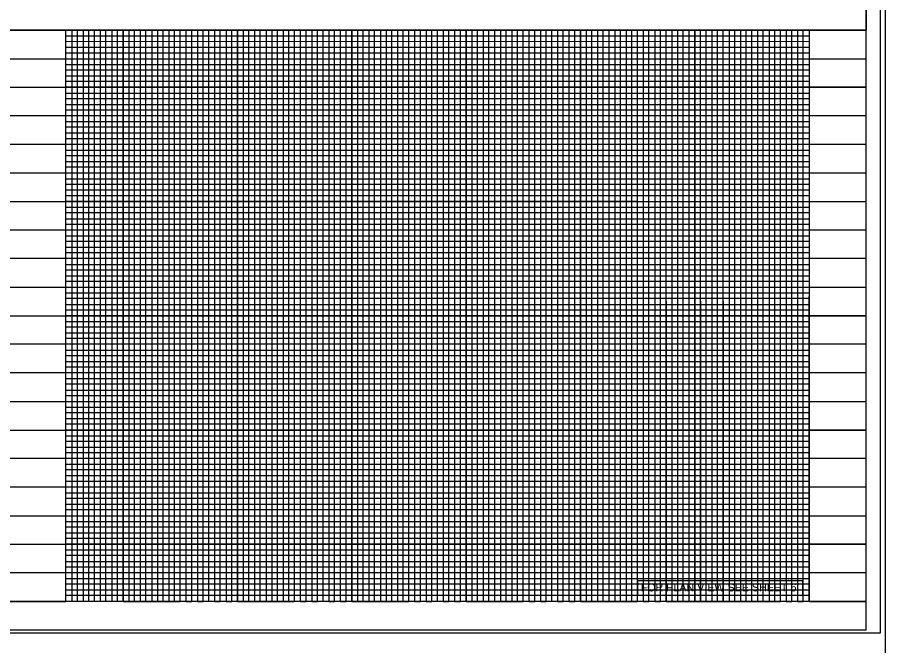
# Model space of a CAD drawing. Extents: x 1755181 to 1757273, y 729911 to 735411.
# Drawn here: x 1756105 to 1756865, y 731022 to 731572 of the extents above; entities that cross this region are included whole.
import ezdxf

# ---------------------------------------------------------------- set-up
doc = ezdxf.new("R2010")
doc.units = 0
for name, color, linetype in [('Prop Grid Mask', 7, 'Continuous'), ('Prop VPI Label', 7, 'Continuous'), ('Scratch_Level_3', 7, 'Continuous'), ('Sheet DOT Grid CELL', 7, 'Continuous'), ('Sheet Plot Border Inside CELL', 7, 'Continuous'), ('Sheet Plot Border Outside CELL', 7, 'Continuous'), ('Sheet Profile CELL', 7, 'Continuous'), ('Sheet Profile Grid Major CELL', 7, 'Continuous'), ('Sheet Profile Grid Middle CELL', 7, 'Continuous'), ('Sheet Profile Grid Minor CELL', 7, 'Continuous')]:
    doc.layers.add(name, color=color, linetype=linetype)

msp = doc.modelspace()

# ---------------------------------------------------------------- linework, layer by layer
at = {"layer": 'Prop Grid Mask'}
msp.add_lwpolyline([(1756647.87, 731079.11), (1756792.01, 731079.11), (1756792.01, 731065.9), (1756647.87, 731065.9)], close=True, dxfattribs=at)
at = {"layer": 'Scratch_Level_3'}
for points in [[(1756097.67, 731560.78), (1756097.67, 732085.78), (1756647.63, 732085.78), (1756647.63, 731852.66), (1756847.68, 731852.66), (1756847.68, 731560.78)], [(1756097.67, 731035.78), (1756847.67, 731035.78), (1756847.67, 731560.78), (1756097.67, 731560.78)]]:
    msp.add_lwpolyline(points, close=True, dxfattribs=at)
at = {"layer": 'Sheet DOT Grid CELL'}
for p, q in [((1755347.67, 731560.78), (1756847.56, 731560.78)), ((1756147.67, 731060.78), (1756147.67, 731560.78)), ((1756197.67, 731060.78), (1756197.67, 731560.78)), ((1756247.67, 731060.78), (1756247.67, 731560.78)), ((1756297.67, 731060.78), (1756297.67, 731560.78)), ((1756347.67, 731060.78), (1756347.67, 731560.78)), ((1756397.67, 731060.78), (1756397.67, 731560.78)), ((1756447.67, 731060.78), (1756447.67, 731560.78)), ((1756497.67, 731060.78), (1756497.67, 731560.78)), ((1756547.67, 731060.78), (1756547.67, 731560.78)), ((1756597.67, 731060.78), (1756597.67, 731560.78)), ((1756697.67, 731060.78), (1756697.67, 731560.78)), ((1756747.67, 731060.78), (1756747.67, 731560.78)), ((1756847.66, 731510.78), (1756147.67, 731510.78)), ((1756647.62, 731460.78), (1756147.67, 731460.78)), ((1756647.67, 731060.78), (1756647.67, 731423.23)), ((1756647.67, 731410.78), (1756147.67, 731410.78)), ((1756797.67, 731060.78), (1756797.67, 731327.66)), ((1756847.67, 731310.78), (1756147.67, 731310.78)), ((1756847.67, 731260.78), (1756147.67, 731260.78)), ((1756847.67, 731210.78), (1756147.67, 731210.78)), ((1756847.67, 731160.78), (1756147.67, 731160.78)), ((1756847.67, 731110.78), (1756147.67, 731110.78))]:
    msp.add_line(p, q, dxfattribs=at)
at = {"layer": 'Sheet Plot Border Inside CELL'}
msp.add_lwpolyline([(1755193.67, 731033.23), (1756860.17, 731033.23), (1756860.17, 732088.33), (1755193.67, 732088.33)], close=True, dxfattribs=at)
at = {"layer": 'Sheet Plot Border Outside CELL'}
msp.add_lwpolyline([(1755180.67, 731010.78), (1756864.67, 731010.78), (1756864.67, 732110.78), (1755180.67, 732110.78)], close=True, dxfattribs=at)
at = {"layer": 'Sheet Profile CELL'}
for p, q in [((1755347.67, 731560.78), (1756847.67, 731560.78)), ((1756847.67, 731060.78), (1755347.67, 731060.78)), ((1755347.67, 731035.78), (1756847.67, 731035.78))]:
    msp.add_line(p, q, dxfattribs=at)
msp.add_lwpolyline([(1756847.67, 732085.78), (1755347.67, 732085.78), (1755347.67, 731035.78), (1756847.67, 731035.78)], close=True, dxfattribs=at)
at = {"layer": 'Sheet Profile Grid Major CELL'}
for p, q in [((1756147.67, 731560.78), (1756197.67, 731560.78)), ((1756247.67, 731560.78), (1756297.67, 731560.78)), ((1756347.67, 731560.78), (1756397.67, 731560.78)), ((1756447.67, 731560.78), (1756497.67, 731560.78)), ((1756547.67, 731560.78), (1756597.67, 731560.78)), ((1756647.67, 731560.78), (1756697.67, 731560.78)), ((1756747.67, 731560.78), (1756797.67, 731560.78)), ((1756747.67, 731060.78), (1756747.67, 731060.78))]:
    msp.add_line(p, q, dxfattribs=at)
for points in [[(1756097.67, 731060.78), (1756147.67, 731060.78), (1756147.67, 731560.78), (1756197.67, 731560.78), (1756197.67, 731060.78), (1756247.67, 731060.78), (1756247.67, 731560.78), (1756297.67, 731560.78), (1756297.67, 731060.78), (1756347.67, 731060.78), (1756347.67, 731560.78), (1756397.67, 731560.78), (1756397.67, 731060.78), (1756447.67, 731060.78), (1756447.67, 731560.78), (1756497.67, 731560.78), (1756497.67, 731060.78), (1756547.67, 731060.78), (1756547.67, 731560.78), (1756597.67, 731560.78), (1756597.67, 731060.78), (1756647.67, 731060.78), (1756647.67, 731560.78), (1756673.97, 731560.78)], [(1756697.67, 731560.78), (1756697.67, 731060.78), (1756747.67, 731060.78), (1756747.67, 731060.78), (1756747.67, 731560.78)], [(1756797.67, 731560.78), (1756797.67, 731060.78), (1756847.67, 731060.78), (1756847.67, 731410.78)], [(1755347.67, 731510.78), (1756847.71, 731510.78)], [(1756847.71, 731460.78), (1755347.67, 731460.78), (1755347.67, 731410.78), (1756847.71, 731410.78)], [(1756847.67, 731360.78), (1755347.67, 731360.78), (1755347.67, 731310.78), (1756847.67, 731310.78)], [(1756847.67, 731260.78), (1755347.67, 731260.78), (1755347.67, 731210.78), (1756847.67, 731210.78)], [(1756847.67, 731160.78), (1755347.67, 731160.78), (1755347.67, 731160.78), (1755347.67, 731110.78), (1756847.67, 731110.78)], [(1756847.67, 731060.78), (1755347.67, 731060.78)]]:
    msp.add_lwpolyline(points, dxfattribs=at)
at = {"layer": 'Sheet Profile Grid Middle CELL'}
for p, q in [((1756172.67, 731060.78), (1756172.67, 731560.78)), ((1756222.67, 731560.78), (1756222.67, 731060.78)), ((1756272.67, 731060.78), (1756272.67, 731560.78)), ((1756322.67, 731560.78), (1756322.67, 731060.78)), ((1756372.67, 731060.78), (1756372.67, 731560.78)), ((1756422.67, 731560.78), (1756422.67, 731060.78)), ((1756472.67, 731060.78), (1756472.67, 731560.78)), ((1756522.67, 731560.78), (1756522.67, 731060.78)), ((1756572.67, 731060.78), (1756572.67, 731560.78)), ((1756622.67, 731560.78), (1756622.67, 731060.78)), ((1756672.67, 731060.78), (1756672.67, 731560.78)), ((1755347.67, 731535.78), (1756847.66, 731535.78))]:
    msp.add_line(p, q, dxfattribs=at)
for points in [[(1756672.67, 731323.58), (1756672.67, 731060.78), (1756722.67, 731060.78), (1756722.67, 731560.78)], [(1756722.67, 731323.58), (1756722.67, 731060.78), (1756772.67, 731060.78), (1756772.67, 731560.78)], [(1756847.71, 731485.78), (1755347.67, 731485.78), (1755347.67, 731435.78), (1756847.71, 731435.78)], [(1756847.66, 731385.78), (1755347.67, 731385.78), (1755347.67, 731335.78), (1756847.67, 731335.78)], [(1756847.67, 731285.78), (1755347.67, 731285.78), (1755347.67, 731235.78), (1756847.67, 731235.78)], [(1756847.67, 731185.78), (1755347.67, 731185.78), (1755347.67, 731135.78), (1756847.67, 731135.78)], [(1756847.67, 731085.78), (1755347.67, 731085.78)]]:
    msp.add_lwpolyline(points, dxfattribs=at)
at = {"layer": 'Sheet Profile Grid Minor CELL'}
for p, q in [((1756152.67, 731560.78), (1756152.67, 731060.78)), ((1756157.67, 731060.78), (1756157.67, 731560.78)), ((1756162.67, 731560.78), (1756162.67, 731060.78)), ((1756167.67, 731060.78), (1756167.67, 731560.78)), ((1756177.67, 731560.78), (1756177.67, 731060.78)), ((1756182.67, 731060.78), (1756182.67, 731560.78)), ((1756187.67, 731560.78), (1756187.67, 731060.78)), ((1756192.67, 731060.78), (1756192.67, 731560.78)), ((1756202.67, 731560.78), (1756202.67, 731060.78)), ((1756207.67, 731060.78), (1756207.67, 731560.78)), ((1756212.67, 731560.78), (1756212.67, 731060.78)), ((1756217.67, 731060.78), (1756217.67, 731560.78)), ((1756227.67, 731560.78), (1756227.67, 731060.78)), ((1756147.67, 731555.78), (1756797.71, 731555.78)), ((1756797.71, 731550.78), (1756147.67, 731550.64)), ((1756147.67, 731545.78), (1756797.71, 731545.78)), ((1756797.66, 731425.78), (1756147.67, 731425.78)), ((1756797.71, 731420.78), (1756147.67, 731420.78)), ((1756797.71, 731415.78), (1756147.67, 731415.78)), ((1756147.67, 731405.78), (1756797.71, 731405.78)), ((1756797.71, 731400.78), (1756147.67, 731400.78)), ((1756147.67, 731395.78), (1756797.66, 731395.78)), ((1756797.66, 731375.78), (1756147.67, 731375.78)), ((1756147.67, 731370.78), (1756797.66, 731370.78)), ((1756797.67, 731350.78), (1756147.67, 731350.78)), ((1756147.67, 731345.78), (1756797.67, 731345.78)), ((1756797.67, 731325.78), (1756147.67, 731325.78)), ((1756147.67, 731320.78), (1756797.67, 731320.78)), ((1756797.67, 731315.78), (1756147.67, 731315.78)), ((1756147.67, 731305.78), (1756797.67, 731305.78)), ((1756797.67, 731300.78), (1756147.67, 731300.78)), ((1756147.67, 731295.78), (1756797.67, 731295.78)), ((1756797.67, 731290.78), (1756147.67, 731290.78)), ((1756147.67, 731280.78), (1756797.67, 731280.78)), ((1756797.67, 731275.78), (1756147.67, 731275.78)), ((1756147.67, 731270.78), (1756797.67, 731270.78)), ((1756797.67, 731265.78), (1756147.67, 731265.78)), ((1756147.67, 731255.78), (1756797.67, 731255.78)), ((1756797.67, 731250.78), (1756147.67, 731250.78)), ((1756147.67, 731245.78), (1756797.67, 731245.78)), ((1756797.67, 731240.78), (1756147.67, 731240.78)), ((1756147.67, 731230.78), (1756797.67, 731230.78)), ((1756797.67, 731225.78), (1756147.67, 731225.78)), ((1756147.67, 731220.78), (1756797.67, 731220.78)), ((1756797.67, 731215.78), (1756147.67, 731215.78)), ((1756147.67, 731205.78), (1756797.67, 731205.78)), ((1756797.67, 731200.78), (1756147.67, 731200.78)), ((1756147.67, 731195.78), (1756797.67, 731195.78)), ((1756797.67, 731190.78), (1756147.67, 731190.78)), ((1756147.67, 731180.78), (1756797.67, 731180.78)), ((1756797.67, 731175.78), (1756147.67, 731175.78)), ((1756797.67, 731170.78), (1756147.67, 731170.78)), ((1756797.67, 731165.78), (1756147.67, 731165.78)), ((1756147.67, 731155.78), (1756797.67, 731155.78)), ((1756797.67, 731150.78), (1756147.67, 731150.78)), ((1756147.67, 731145.78), (1756797.67, 731145.78)), ((1756797.67, 731140.78), (1756147.67, 731140.78)), ((1756147.67, 731130.78), (1756797.67, 731130.78)), ((1756797.67, 731125.78), (1756147.67, 731125.78)), ((1756147.67, 731120.78), (1756797.67, 731120.78)), ((1756797.67, 731115.78), (1756147.67, 731115.78)), ((1756147.67, 731105.78), (1756797.67, 731105.78)), ((1756797.67, 731100.78), (1756147.67, 731100.78)), ((1756147.67, 731095.78), (1756797.67, 731095.78)), ((1756797.67, 731090.78), (1756147.67, 731090.78)), ((1756147.67, 731080.78), (1756797.67, 731080.78)), ((1756797.67, 731075.78), (1756147.67, 731075.78)), ((1756147.67, 731070.78), (1756797.67, 731070.78))]:
    msp.add_line(p, q, dxfattribs=at)
for points in [[(1756232.67, 731060.78), (1756232.67, 731560.78), (1756237.67, 731560.78), (1756237.67, 731060.78), (1756242.67, 731060.78), (1756242.67, 731560.78), (1756252.67, 731560.78), (1756252.67, 731060.78), (1756257.67, 731060.78), (1756257.67, 731560.78), (1756262.67, 731560.78), (1756262.67, 731060.78), (1756267.67, 731060.78), (1756267.67, 731560.78), (1756277.67, 731560.78), (1756277.67, 731060.78), (1756282.67, 731060.78), (1756282.67, 731560.78), (1756287.67, 731560.78), (1756287.67, 731060.78), (1756292.67, 731060.78), (1756292.67, 731560.78), (1756302.67, 731560.78), (1756302.67, 731060.78), (1756307.67, 731060.78), (1756307.67, 731560.78), (1756312.67, 731560.78), (1756312.67, 731060.78), (1756317.67, 731060.78), (1756317.67, 731560.78), (1756327.67, 731560.78), (1756327.67, 731060.78), (1756332.67, 731060.78), (1756332.67, 731560.78), (1756337.67, 731560.78), (1756337.67, 731060.78), (1756342.67, 731060.78), (1756342.67, 731560.78), (1756352.67, 731560.78), (1756352.67, 731060.78), (1756357.67, 731060.78), (1756357.67, 731560.78), (1756362.67, 731560.78), (1756362.67, 731060.78), (1756367.67, 731060.78), (1756367.67, 731560.78), (1756377.67, 731560.78), (1756377.67, 731060.78), (1756382.67, 731060.78), (1756382.67, 731560.78), (1756387.67, 731560.78), (1756387.67, 731060.78), (1756392.67, 731060.78), (1756392.67, 731560.78), (1756402.67, 731560.78), (1756402.67, 731060.78), (1756407.67, 731060.78), (1756407.67, 731560.78), (1756412.67, 731560.78), (1756412.67, 731060.78), (1756417.67, 731060.78), (1756417.67, 731560.78), (1756427.67, 731560.78), (1756427.67, 731060.78), (1756432.67, 731060.78), (1756432.67, 731560.78), (1756437.67, 731560.78), (1756437.67, 731060.78), (1756442.67, 731060.78), (1756442.67, 731560.78), (1756452.67, 731560.78), (1756452.67, 731060.78), (1756457.67, 731060.78), (1756457.67, 731560.78), (1756462.67, 731560.78), (1756462.67, 731060.78), (1756467.67, 731060.78), (1756467.67, 731560.78), (1756477.67, 731560.78), (1756477.67, 731060.78), (1756482.67, 731060.78), (1756482.67, 731560.78), (1756487.67, 731560.78), (1756487.67, 731060.78), (1756492.67, 731060.78), (1756492.67, 731560.78), (1756502.67, 731560.78), (1756502.67, 731060.78), (1756507.67, 731060.78), (1756507.67, 731560.78), (1756512.67, 731560.78), (1756512.67, 731060.78), (1756517.67, 731060.78), (1756517.67, 731560.78), (1756527.67, 731560.78), (1756527.67, 731060.78), (1756532.67, 731060.78), (1756532.67, 731560.78), (1756537.67, 731560.78), (1756537.67, 731060.78)], [(1756537.67, 731060.78), (1756542.67, 731060.78), (1756542.67, 731560.78), (1756552.67, 731560.78), (1756552.67, 731060.78), (1756557.67, 731060.78), (1756557.67, 731560.78), (1756562.67, 731560.78), (1756562.67, 731060.78), (1756567.67, 731060.78), (1756567.67, 731560.78), (1756577.67, 731560.78), (1756577.67, 731060.78), (1756582.67, 731060.78), (1756582.67, 731560.78), (1756587.67, 731560.78), (1756587.67, 731060.78), (1756592.67, 731060.78), (1756592.67, 731560.78), (1756602.67, 731560.78), (1756602.67, 731060.78), (1756607.67, 731060.78), (1756607.67, 731560.78), (1756612.67, 731560.78), (1756612.67, 731060.78), (1756617.67, 731060.78), (1756617.67, 731560.78), (1756627.67, 731560.78), (1756627.67, 731060.78), (1756632.67, 731060.78), (1756632.67, 731560.78), (1756637.67, 731560.78), (1756637.67, 731060.78), (1756642.67, 731060.78), (1756642.67, 731560.78), (1756652.67, 731560.78)], [(1756652.67, 731560.78), (1756652.67, 731060.78), (1756657.67, 731060.78), (1756657.67, 731560.78)], [(1756662.67, 731560.78), (1756662.67, 731060.78), (1756667.67, 731060.78), (1756667.67, 731560.78)], [(1756677.67, 731560.78), (1756677.67, 731060.78), (1756677.67, 731060.78), (1756682.67, 731060.78), (1756687.67, 731060.78), (1756687.67, 731560.78)], [(1756682.67, 731560.78), (1756682.67, 731060.78)], [(1756692.64, 731560.78), (1756692.57, 731060.83), (1756697.57, 731060.83), (1756702.67, 731060.78), (1756702.67, 731560.78)], [(1756702.67, 731323.58), (1756702.67, 731060.78), (1756707.67, 731060.78), (1756707.67, 731560.78)], [(1756712.67, 731560.78), (1756712.67, 731060.78), (1756717.67, 731060.78), (1756717.67, 731560.78)], [(1756727.67, 731560.78), (1756727.67, 731060.78), (1756732.67, 731060.78), (1756732.67, 731560.78)], [(1756737.67, 731560.78), (1756737.67, 731060.78), (1756742.67, 731060.78), (1756742.67, 731560.78)], [(1756752.67, 731560.78), (1756752.67, 731060.78), (1756757.67, 731060.78), (1756757.67, 731560.78)], [(1756762.67, 731560.78), (1756762.67, 731060.78), (1756767.67, 731060.78), (1756767.67, 731560.78)], [(1756777.67, 731560.78), (1756777.67, 731060.78), (1756782.67, 731060.78), (1756782.67, 731560.78)], [(1756787.67, 731560.78), (1756787.67, 731060.78), (1756792.67, 731060.78), (1756792.67, 731560.78)], [(1756797.71, 731540.78), (1756147.67, 731540.78)], [(1756147.67, 731530.78), (1756797.71, 731530.78)], [(1756797.66, 731525.78), (1756147.67, 731525.78)], [(1756147.67, 731520.78), (1756797.71, 731520.78)], [(1756797.71, 731515.78), (1756147.67, 731515.78)], [(1756147.67, 731505.78), (1756797.71, 731505.78)], [(1756797.71, 731500.78), (1756147.67, 731500.78)], [(1756147.67, 731495.78), (1756797.71, 731495.78)], [(1756797.71, 731490.78), (1756147.67, 731490.78)], [(1756147.67, 731480.78), (1756797.71, 731480.78)], [(1756797.71, 731475.78), (1756147.67, 731475.78)], [(1756147.67, 731470.78), (1756797.71, 731470.78)], [(1756797.71, 731465.78), (1756147.67, 731465.78)], [(1756147.67, 731455.78), (1756797.71, 731455.78)], [(1756797.71, 731450.68), (1756147.67, 731450.68)], [(1756147.67, 731445.78), (1756797.71, 731445.78)], [(1756797.71, 731440.78), (1756147.67, 731440.78)], [(1756147.67, 731430.78), (1756797.71, 731430.78)], [(1756797.66, 731390.78), (1756147.67, 731390.78)], [(1756147.67, 731380.78), (1756797.66, 731380.78)], [(1756797.66, 731365.78), (1756147.67, 731365.78)], [(1756147.67, 731355.78), (1756797.67, 731355.78)], [(1756797.67, 731340.78), (1756147.67, 731340.78)], [(1756147.67, 731330.78), (1756797.67, 731330.78)], [(1756797.67, 731065.78), (1756147.67, 731065.78)]]:
    msp.add_lwpolyline(points, dxfattribs=at)

# ---------------------------------------------------------------- texts
at = {"layer": 'Prop VPI Label'}
msp.add_text('FOR PLAN VIEW SEE SHEET 6', height=7, dxfattribs=at).set_placement((1756650.41, 731069.48))

doc.saveas('drawing.dxf')
